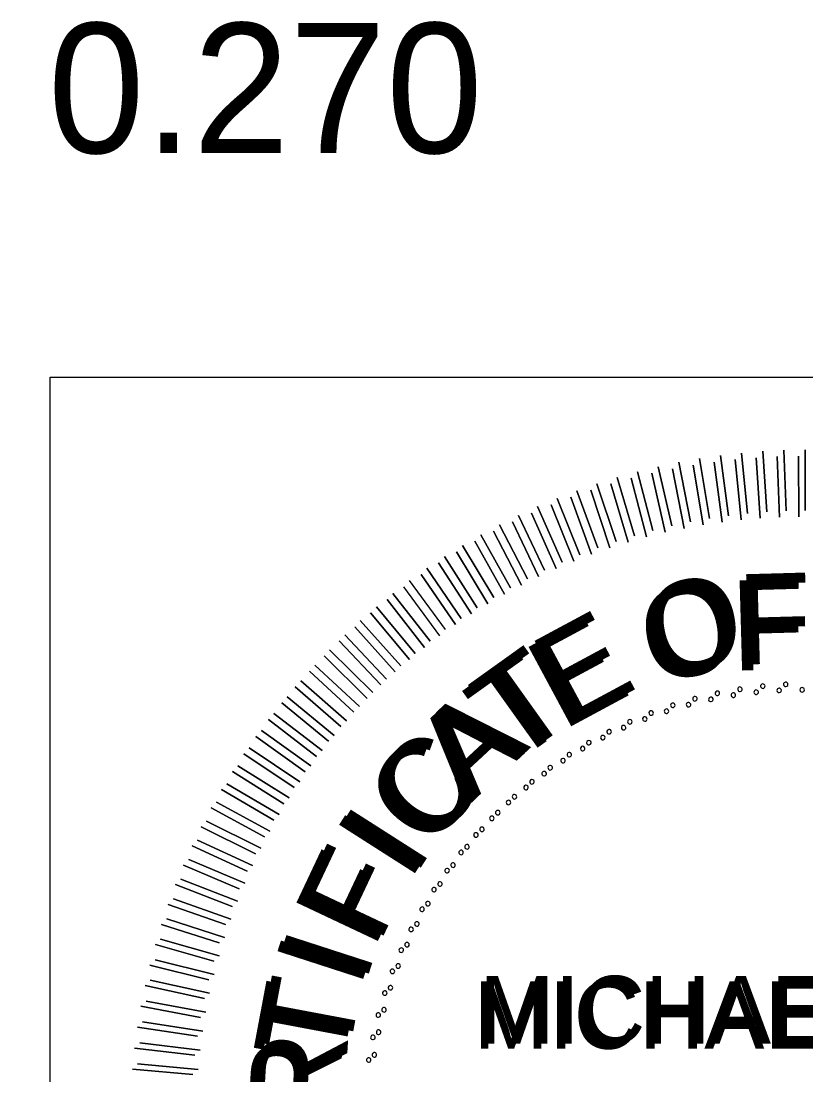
# Model space of a CAD drawing. Extents: x -2512 to 3792, y -435 to 2624.
# Drawn here: x 2724.7 to 2869.7, y 359.8 to 554.4 of the extents above; entities that cross this region are included whole.
import ezdxf

# ---------------------------------------------------------------- set-up
doc = ezdxf.new("R2010")
doc.units = 0
for name, color, linetype in [('G-ANNO-TEXT', 7, 'Continuous'), ('R_Annotation', 7, 'Continuous'), ('R_No Plot', 7, 'Continuous'), ('STAMP_BOL', 7, 'Continuous')]:
    doc.layers.add(name, color=color, linetype=linetype)

msp = doc.modelspace()

# ---------------------------------------------------------------- linework, layer by layer
at = {"layer": 'G-ANNO-TEXT'}
for points in [[(2854.17, 461.91), (2852.7, 473.01)], [(2852.7, 473.01), (2854.17, 461.91)], [(2857.69, 462.32), (2856.58, 473.46)], [(2856.58, 473.46), (2857.69, 462.32)], [(2861.23, 462.62), (2860.46, 473.79)], [(2860.46, 473.79), (2861.23, 462.62)], [(2864.77, 462.81), (2864.36, 474)], [(2864.36, 474), (2864.77, 462.81)], [(2868.32, 462.88), (2868.26, 474.08)], [(2868.26, 474.08), (2868.32, 462.88)], [(2843.69, 460.03), (2841.19, 470.94)], [(2841.19, 470.94), (2843.69, 460.03)], [(2847.17, 460.76), (2845.01, 471.75)], [(2845.01, 471.75), (2847.17, 460.76)], [(2850.66, 461.39), (2848.84, 472.44)], [(2848.84, 472.44), (2850.66, 461.39)], [(2836.83, 458.22), (2833.65, 468.96)], [(2833.65, 468.96), (2836.83, 458.22)], [(2840.25, 459.18), (2837.4, 470.01)], [(2837.4, 470.01), (2840.25, 459.18)], [(2833.45, 457.16), (2829.93, 467.79)], [(2829.93, 467.79), (2833.45, 457.16)], [(2826.78, 454.72), (2822.6, 465.11)], [(2822.6, 465.11), (2826.78, 454.72)], [(2830.09, 455.99), (2826.24, 466.51)], [(2826.24, 466.51), (2830.09, 455.99)], [(2823.51, 453.34), (2819.01, 463.59)], [(2819.01, 463.59), (2823.51, 453.34)], [(2820.29, 451.86), (2815.46, 461.97)], [(2815.46, 461.97), (2820.29, 451.86)], [(2817.11, 450.29), (2811.97, 460.23)], [(2811.97, 460.23), (2817.11, 450.29)], [(2813.98, 448.61), (2808.53, 458.39)], [(2808.53, 458.39), (2813.98, 448.61)], [(2810.91, 446.83), (2805.15, 456.44)], [(2805.15, 456.44), (2810.91, 446.83)], [(2807.89, 444.96), (2801.84, 454.38)], [(2801.84, 454.38), (2807.89, 444.96)], [(2804.94, 443), (2798.59, 452.22)], [(2798.59, 452.22), (2804.94, 443)], [(2802.05, 440.94), (2795.41, 449.96)], [(2799.22, 438.79), (2792.31, 447.6)], [(2792.31, 447.6), (2799.22, 438.79)], [(2796.46, 436.56), (2789.28, 445.15)], [(2789.28, 445.15), (2796.46, 436.56)], [(2793.78, 434.24), (2786.33, 442.6)], [(2786.33, 442.6), (2793.78, 434.24)], [(2791.17, 431.84), (2783.46, 439.96)], [(2783.46, 439.96), (2791.17, 431.84)], [(2788.63, 429.35), (2780.67, 437.23)], [(2780.67, 437.23), (2788.63, 429.35)], [(2786.18, 426.79), (2777.97, 434.41)], [(2777.97, 434.41), (2786.18, 426.79)], [(2783.8, 424.15), (2775.36, 431.51)], [(2775.36, 431.51), (2783.8, 424.15)], [(2781.51, 421.44), (2772.85, 428.53)], [(2772.85, 428.53), (2781.51, 421.44)], [(2779.31, 418.66), (2770.42, 425.47)], [(2770.42, 425.47), (2779.31, 418.66)], [(2777.2, 415.81), (2768.1, 422.34)], [(2768.1, 422.34), (2777.2, 415.81)], [(2775.17, 412.9), (2765.88, 419.14)], [(2765.88, 419.14), (2775.17, 412.9)], [(2773.24, 409.92), (2763.75, 415.87)], [(2763.75, 415.87), (2773.24, 409.92)], [(2771.4, 406.88), (2761.73, 412.53)], [(2761.73, 412.53), (2771.4, 406.88)], [(2769.66, 403.79), (2759.82, 409.13)], [(2759.82, 409.13), (2769.66, 403.79)], [(2768.02, 400.65), (2758.01, 405.67)], [(2758.01, 405.67), (2768.02, 400.65)], [(2766.47, 397.45), (2756.32, 402.16)], [(2756.32, 402.16), (2766.47, 397.45)], [(2765.03, 394.21), (2754.73, 398.6)], [(2754.73, 398.6), (2765.03, 394.21)], [(2763.69, 390.92), (2753.26, 394.99)], [(2753.26, 394.99), (2763.69, 390.92)], [(2762.46, 387.6), (2751.9, 391.33)], [(2751.9, 391.33), (2762.46, 387.6)], [(2761.33, 384.23), (2750.66, 387.63)], [(2750.66, 387.63), (2761.33, 384.23)], [(2760.3, 380.83), (2749.53, 383.9)], [(2749.53, 383.9), (2760.3, 380.83)], [(2759.38, 377.41), (2748.52, 380.13)], [(2748.52, 380.13), (2759.38, 377.41)], [(2758.58, 373.95), (2747.63, 376.33)], [(2747.63, 376.33), (2758.58, 373.95)], [(2757.87, 370.47), (2746.86, 372.51)], [(2746.86, 372.51), (2757.87, 370.47)], [(2757.28, 366.97), (2746.22, 368.66)], [(2746.22, 368.66), (2757.28, 366.97)], [(2756.8, 363.46), (2745.69, 364.8)], [(2745.69, 364.8), (2756.8, 363.46)], [(2756.43, 359.93), (2745.28, 360.92)], [(2745.28, 360.92), (2756.43, 359.93)]]:
    msp.add_lwpolyline(points, dxfattribs=at)
for centre, start, end in [((2856.27, 429.96), 9, 189), ((2860.48, 430.51), 6, 186), ((2860.48, 430.51), 186, 6), ((2864.71, 430.84), 3, 183), ((2864.71, 430.84), 183, 3), ((2868.95, 430.95), 0, 180), ((2868.95, 430.95), 180, 0), ((2847.98, 428.19), 15, 195), ((2847.98, 428.19), 195, 15), ((2852.1, 429.18), 12, 192), ((2852.1, 429.18), 192, 12), ((2856.27, 429.96), 189, 9), ((2843.91, 426.99), 18, 198), ((2843.91, 426.99), 198, 18), ((2835.99, 423.95), 24, 204), ((2839.91, 425.57), 21, 201), ((2839.91, 425.57), 201, 21), ((2832.16, 422.12), 27, 207), ((2832.16, 422.12), 207, 27), ((2835.99, 423.95), 204, 24), ((2828.44, 420.1), 30, 210), ((2828.44, 420.1), 210, 30), ((2824.82, 417.88), 33, 213), ((2824.82, 417.88), 213, 33), ((2821.32, 415.48), 36, 216), ((2821.32, 415.48), 216, 36), ((2817.96, 412.9), 39, 219), ((2817.96, 412.9), 219, 39), ((2814.73, 410.14), 42, 222), ((2814.73, 410.14), 222, 42), ((2811.65, 407.22), 45, 225), ((2811.65, 407.22), 225, 45), ((2808.73, 404.14), 48, 228), ((2808.73, 404.14), 228, 48), ((2805.98, 400.92), 51, 231), ((2805.98, 400.92), 231, 51), ((2803.4, 397.55), 54, 234), ((2803.4, 397.55), 234, 54), ((2800.99, 394.06), 57, 237), ((2800.99, 394.06), 237, 57), ((2798.78, 390.44), 60, 240), ((2798.78, 390.44), 240, 60), ((2796.75, 386.71), 63, 243), ((2796.75, 386.71), 243, 63), ((2794.93, 382.88), 66, 246), ((2794.93, 382.88), 246, 66), ((2793.3, 378.96), 69, 249), ((2793.3, 378.96), 249, 69), ((2791.89, 374.96), 72, 252), ((2791.89, 374.96), 252, 72), ((2790.68, 370.9), 75, 255), ((2790.68, 370.9), 255, 75), ((2789.69, 366.77), 78, 258), ((2789.69, 366.77), 258, 78), ((2788.92, 362.6), 81, 261), ((2788.92, 362.6), 261, 81)]:
    msp.add_arc(centre, 0.416, start, end, dxfattribs=at)
at = {"layer": 'R_No Plot'}
msp.add_lwpolyline([(2730.1, 488.67), (3010.37, 488.67), (3010.37, 212.74), (2730.1, 212.74)], close=True, dxfattribs=at)
at = {"layer": 'STAMP_BOL'}
for points in [[(2862.44, 463.8), (2861.68, 475)], [(2861.68, 475), (2862.44, 463.8)], [(2865.99, 463.99), (2865.58, 475.2)], [(2865.58, 475.2), (2865.99, 463.99)], [(2869.55, 464.06), (2869.49, 475.28)], [(2869.49, 475.28), (2869.55, 464.06)], [(2848.35, 461.94), (2846.18, 472.95)], [(2846.18, 472.95), (2848.35, 461.94)], [(2851.85, 462.57), (2850.03, 473.64)], [(2850.03, 473.64), (2851.85, 462.57)], [(2855.37, 463.09), (2853.9, 474.22)], [(2853.9, 474.22), (2855.37, 463.09)], [(2858.9, 463.5), (2857.78, 474.67)], [(2857.78, 474.67), (2858.9, 463.5)], [(2841.41, 460.35), (2838.56, 471.2)], [(2838.56, 471.2), (2841.41, 460.35)], [(2844.87, 461.2), (2842.36, 472.14)], [(2842.36, 472.14), (2844.87, 461.2)], [(2834.59, 458.33), (2831.07, 468.98)], [(2831.07, 468.98), (2834.59, 458.33)], [(2837.99, 459.39), (2834.8, 470.15)], [(2834.8, 470.15), (2837.99, 459.39)], [(2831.24, 457.16), (2827.38, 467.69)], [(2827.38, 467.69), (2831.24, 457.16)], [(2827.92, 455.88), (2823.73, 466.29)], [(2823.73, 466.29), (2827.92, 455.88)], [(2821.4, 453.02), (2816.57, 463.15)], [(2816.57, 463.15), (2821.4, 453.02)], [(2824.64, 454.5), (2820.12, 464.77)], [(2820.12, 464.77), (2824.64, 454.5)], [(2818.22, 451.44), (2813.07, 461.41)], [(2813.07, 461.41), (2818.22, 451.44)], [(2815.09, 449.75), (2809.62, 459.56)], [(2809.62, 459.56), (2815.09, 449.75)], [(2812.01, 447.97), (2806.24, 457.6)], [(2806.24, 457.6), (2812.01, 447.97)], [(2808.98, 446.1), (2802.92, 455.54)], [(2802.92, 455.54), (2808.98, 446.1)], [(2806.02, 444.13), (2799.66, 453.38)], [(2799.66, 453.38), (2806.02, 444.13)], [(2803.12, 442.07), (2796.48, 451.11)], [(2800.29, 439.92), (2793.36, 448.75)], [(2793.36, 448.75), (2800.29, 439.92)], [(2797.53, 437.68), (2790.33, 446.29)], [(2790.33, 446.29), (2797.53, 437.68)], [(2794.84, 435.35), (2787.37, 443.73)], [(2787.37, 443.73), (2794.84, 435.35)], [(2792.22, 432.94), (2784.49, 441.08)], [(2784.49, 441.08), (2792.22, 432.94)], [(2789.68, 430.46), (2781.7, 438.35)], [(2781.7, 438.35), (2789.68, 430.46)], [(2787.22, 427.89), (2778.99, 435.52)], [(2778.99, 435.52), (2787.22, 427.89)], [(2784.84, 425.24), (2776.38, 432.62)], [(2776.38, 432.62), (2784.84, 425.24)], [(2782.54, 422.53), (2773.86, 429.63)], [(2773.86, 429.63), (2782.54, 422.53)], [(2780.34, 419.74), (2771.43, 426.57)], [(2771.43, 426.57), (2780.34, 419.74)], [(2778.22, 416.88), (2769.1, 423.43)], [(2769.1, 423.43), (2778.22, 416.88)], [(2776.19, 413.96), (2766.87, 420.22)], [(2766.87, 420.22), (2776.19, 413.96)], [(2774.25, 410.98), (2764.74, 416.94)], [(2764.74, 416.94), (2774.25, 410.98)], [(2772.41, 407.93), (2762.72, 413.59)], [(2762.72, 413.59), (2772.41, 407.93)], [(2770.66, 404.84), (2760.8, 410.19)], [(2760.8, 410.19), (2770.66, 404.84)], [(2769.02, 401.68), (2758.99, 406.72)], [(2758.99, 406.72), (2769.02, 401.68)], [(2767.47, 398.48), (2757.29, 403.2)], [(2757.29, 403.2), (2767.47, 398.48)], [(2766.03, 395.23), (2755.7, 399.63)], [(2755.7, 399.63), (2766.03, 395.23)], [(2764.68, 391.94), (2754.22, 396.01)], [(2754.22, 396.01), (2764.68, 391.94)], [(2763.44, 388.6), (2752.86, 392.35)], [(2752.86, 392.35), (2763.44, 388.6)], [(2762.31, 385.23), (2751.62, 388.64)], [(2751.62, 388.64), (2762.31, 385.23)], [(2761.28, 381.83), (2750.49, 384.9)], [(2750.49, 384.9), (2761.28, 381.83)], [(2760.36, 378.39), (2749.48, 381.12)], [(2749.48, 381.12), (2760.36, 378.39)], [(2759.55, 374.93), (2748.59, 377.31)], [(2748.59, 377.31), (2759.55, 374.93)], [(2758.85, 371.44), (2747.82, 373.48)], [(2747.82, 373.48), (2758.85, 371.44)], [(2758.26, 367.93), (2747.17, 369.63)], [(2747.17, 369.63), (2758.26, 367.93)], [(2757.78, 364.41), (2746.64, 365.75)], [(2746.64, 365.75), (2757.78, 364.41)], [(2757.41, 360.87), (2746.23, 361.87)], [(2746.23, 361.87), (2757.41, 360.87)]]:
    msp.add_lwpolyline(points, dxfattribs=at)
for centre, start, end in [((2861.69, 431.62), 6, 186), ((2865.93, 431.95), 3, 183), ((2853.3, 430.29), 12, 192), ((2853.3, 430.29), 192, 12), ((2857.48, 431.06), 9, 189), ((2857.48, 431.06), 189, 9), ((2861.69, 431.62), 186, 6), ((2865.93, 431.95), 183, 3), ((2845.08, 428.09), 18, 198), ((2845.08, 428.09), 198, 18), ((2849.16, 429.29), 15, 195), ((2849.16, 429.29), 195, 15), ((2841.08, 426.67), 21, 201), ((2841.08, 426.67), 201, 21), ((2837.15, 425.04), 24, 204), ((2837.15, 425.04), 204, 24), ((2833.31, 423.21), 27, 207), ((2833.31, 423.21), 207, 27), ((2829.57, 421.18), 30, 210), ((2829.57, 421.18), 210, 30), ((2825.95, 418.96), 33, 213), ((2825.95, 418.96), 213, 33), ((2822.44, 416.55), 36, 216), ((2822.44, 416.55), 216, 36), ((2819.07, 413.96), 39, 219), ((2819.07, 413.96), 219, 39), ((2815.84, 411.2), 42, 222), ((2815.84, 411.2), 222, 42), ((2812.75, 408.27), 45, 225), ((2812.75, 408.27), 225, 45), ((2809.83, 405.19), 48, 228), ((2809.83, 405.19), 228, 48), ((2807.07, 401.96), 51, 231), ((2807.07, 401.96), 231, 51), ((2804.48, 398.58), 54, 234), ((2804.48, 398.58), 234, 54), ((2802.07, 395.08), 57, 237), ((2802.07, 395.08), 237, 57), ((2799.85, 391.45), 60, 240), ((2799.85, 391.45), 240, 60), ((2797.82, 387.72), 63, 243), ((2797.82, 387.72), 243, 63), ((2795.99, 383.88), 66, 246), ((2795.99, 383.88), 246, 66), ((2794.36, 379.95), 69, 249), ((2794.36, 379.95), 249, 69), ((2792.94, 375.94), 72, 252), ((2792.94, 375.94), 252, 72), ((2791.73, 371.87), 75, 255), ((2791.73, 371.87), 255, 75), ((2790.74, 367.73), 78, 258), ((2790.74, 367.73), 258, 78), ((2789.97, 363.55), 81, 261), ((2789.97, 363.55), 261, 81)]:
    msp.add_arc(centre, 0.417, start, end, dxfattribs=at)

# ---------------------------------------------------------------- texts
at = {"layer": 'G-ANNO-TEXT'}
for s, rotation, p in [('F', 1.5867, (2856.05, 434.46)), ('O', 10.7295, (2840.86, 432.06)), ('E', 28.279, (2824.71, 423.35)), ('T', 35.5725, (2815.43, 416.91)), ('A', 42.8659, (2806.98, 409.23)), ('C', 50.1594, (2799.98, 400.92)), ('I', 57.4529, (2796.37, 395.36)), ('F', 64.7464, (2789.84, 382.92)), ('I', 72.0398, (2787.27, 375.61)), ('T', 79.3333, (2783.96, 361.29)), ('R', 86.6268, (2783.2, 350.29))]:
    msp.add_text(s, height=16.63, rotation=rotation, dxfattribs=at).set_placement(p)
msp.add_text('MICHAEL BAKER', height=12.473, dxfattribs=at).set_placement((2808.26, 364.67))
at = {"layer": 'R_Annotation'}
msp.add_text('LOG MILE 0.270', height=24, dxfattribs=at).set_placement((2569.17, 530.06))
at = {"layer": 'STAMP_BOL'}
for s, rotation, p in [('O', 10.7295, (2842.02, 433.17)), ('F', 1.5867, (2857.25, 435.58)), ('E', 28.279, (2825.84, 424.44)), ('T', 35.5725, (2816.53, 417.99)), ('A', 42.8659, (2808.07, 410.28)), ('C', 50.1594, (2801.06, 401.95)), ('I', 57.4529, (2797.44, 396.38)), ('F', 64.7464, (2790.89, 383.92)), ('I', 72.0398, (2788.31, 376.59)), ('T', 79.3333, (2785, 362.23)), ('R', 86.6268, (2784.23, 351.21))]:
    msp.add_text(s, height=16.67, rotation=rotation, dxfattribs=at).set_placement(p)
msp.add_text('MICHAEL BAKER', height=12.5016, dxfattribs=at).set_placement((2809.35, 365.62))

doc.saveas('drawing.dxf')
